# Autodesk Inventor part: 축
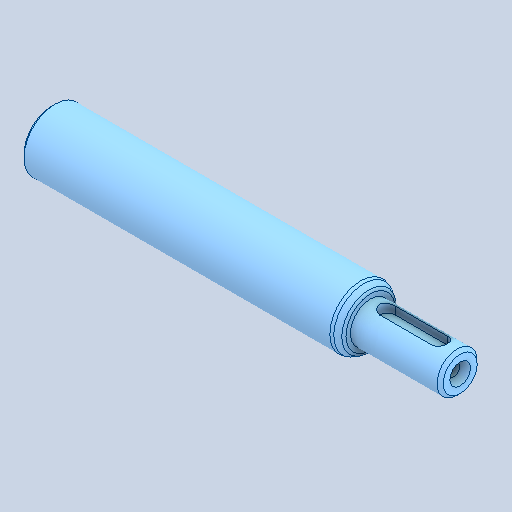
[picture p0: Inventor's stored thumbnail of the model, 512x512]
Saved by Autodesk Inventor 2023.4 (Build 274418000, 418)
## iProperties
Created: 2024-09
Part Number: 축
Material: 강철, 탄소
Document SubType Name: Modeling
Designer: 11
Density: 7.85 g/cm^3
Appearance: 기본값
Author: jhkim
Sending System: Autodesk Inventor 2025
Preprocessor: ST-DEVELOPER v20
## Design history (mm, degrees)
node "축1"
node "솔리드2"
node "솔리드1"
